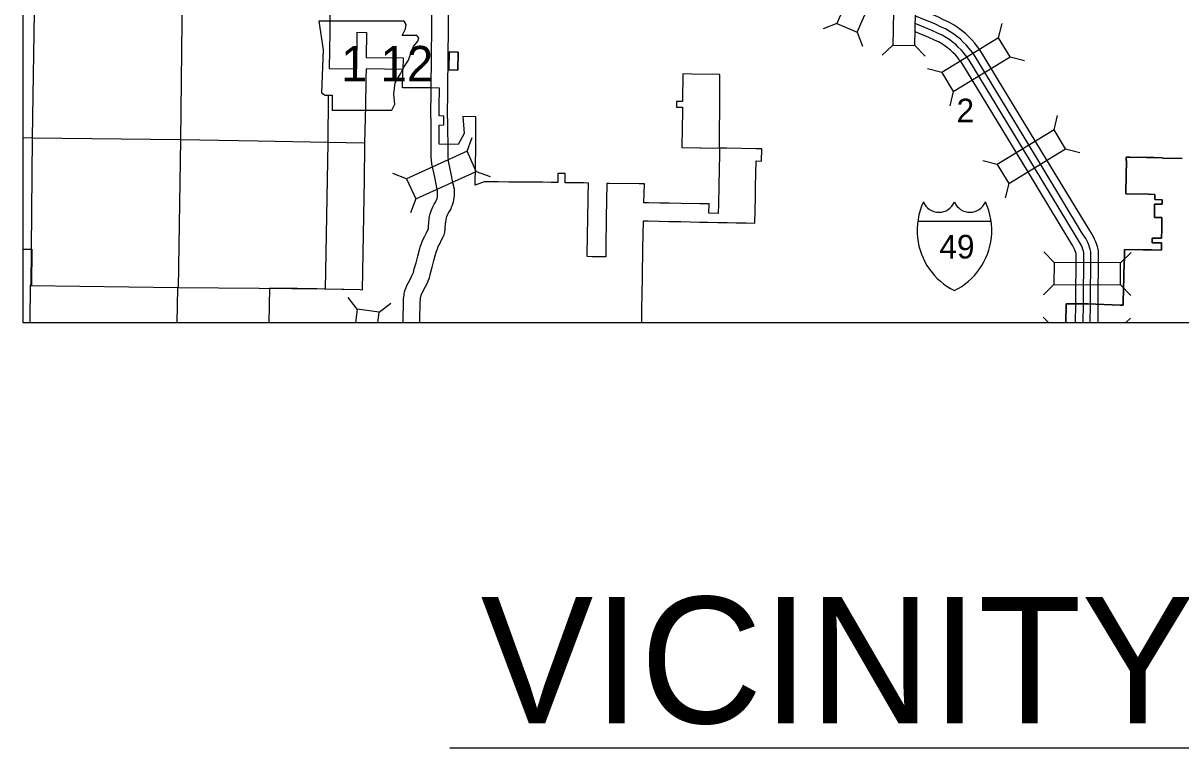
# Model space of a CAD drawing. Extents: x 309389.3 to 309420.2, y 336441.4 to 336461.2.
# Drawn here: x 309389.335 to 309392.47, y 336454.22 to 336456.181 of the extents above; entities that cross this region are included whole.
import ezdxf

# ---------------------------------------------------------------- set-up
doc = ezdxf.new("R2010")
doc.units = 0
for name, color, linetype in [('Level 1', 7, 'Continuous'), ('Level 24', 7, 'Continuous'), ('Level 37', 7, 'Continuous'), ('Level 4', 7, 'Continuous'), ('Level 48', 7, 'Continuous'), ('Level 62', 7, 'Continuous'), ('Level 63', 7, 'Continuous'), ('R_Contours', 7, 'Continuous'), ('R_Erosion', 7, 'Continuous'), ('R_MOT', 7, 'Continuous'), ('R_ROW', 7, 'Continuous')]:
    doc.layers.add(name, color=color, linetype=linetype)

msp = doc.modelspace()

# ---------------------------------------------------------------- linework, layer by layer
at = {"layer": 'Level 24'}
msp.add_line((309390.5454, 336455.969), (309390.5454, 336455.969), dxfattribs=at)
for points in [[(309390.439, 336455.9235), (309390.4424, 336456.2542), (309390.4447, 336456.4403), (309390.4463, 336456.4487), (309390.4504, 336456.4584), (309390.4579, 336456.466), (309390.4642, 336456.4703), (309390.4707, 336456.4735), (309390.4778, 336456.4762)], [(309390.4844, 336455.923), (309390.4879, 336456.2537), (309390.4901, 336456.4322), (309390.4929, 336456.4333), (309390.5042, 336456.4373), (309390.5124, 336456.4426), (309390.5169, 336456.4478)], [(309390.439, 336455.9235), (309390.4394, 336455.819), (309390.4412, 336455.8006), (309390.4488, 336455.7643), (309390.4537, 336455.7407), (309390.4565, 336455.7275), (309390.4565, 336455.7158), (309390.456, 336455.7122), (309390.455, 336455.7055), (309390.4521, 336455.6977)], [(309390.4844, 336455.923), (309390.4848, 336455.8217), (309390.4862, 336455.8075), (309390.4933, 336455.7736), (309390.4982, 336455.75), (309390.5019, 336455.7322), (309390.5019, 336455.7129), (309390.5007, 336455.7035), (309390.4993, 336455.6963), (309390.4961, 336455.686)], [(309390.3642, 336455.3696), (309390.3642, 336455.3742), (309390.3641, 336455.3928), (309390.3648, 336455.4112), (309390.3651, 336455.4286), (309390.3654, 336455.4351), (309390.3659, 336455.4398), (309390.3665, 336455.4444), (309390.3673, 336455.4487), (309390.3682, 336455.4536), (309390.3697, 336455.4593), (309390.3721, 336455.4652), (309390.3745, 336455.4708), (309390.3832, 336455.4874), (309390.3881, 336455.4969), (309390.3896, 336455.5008), (309390.3919, 336455.5064), (309390.3944, 336455.5159), (309390.3991, 336455.5326), (309390.4035, 336455.5503), (309390.4082, 336455.5671), (309390.4104, 336455.5747), (309390.4145, 336455.587), (309390.4186, 336455.5962), (309390.423, 336455.6046), (309390.4275, 336455.6139), (309390.4314, 336455.622), (309390.4324, 336455.6241), (309390.4325, 336455.6257), (309390.4326, 336455.6302), (309390.4333, 336455.6407), (309390.4347, 336455.6514), (309390.4358, 336455.6578), (309390.4371, 336455.6647), (309390.4397, 336455.6734), (309390.4443, 336455.6838), (309390.448, 336455.6907), (309390.4517, 336455.6966), (309390.4521, 336455.6977)], [(309390.4097, 336455.3696), (309390.4097, 336455.3744), (309390.4096, 336455.3922), (309390.4102, 336455.4099), (309390.4105, 336455.427), (309390.4108, 336455.4315), (309390.4111, 336455.4347), (309390.4114, 336455.4373), (309390.412, 336455.4403), (309390.4126, 336455.4439), (309390.4129, 336455.4449), (309390.4141, 336455.4478), (309390.4156, 336455.4513), (309390.4236, 336455.4664), (309390.4297, 336455.4784), (309390.4318, 336455.4839), (309390.4351, 336455.4918), (309390.4383, 336455.5041), (309390.443, 336455.5209), (309390.4475, 336455.5387), (309390.4519, 336455.5547), (309390.4539, 336455.5613), (309390.457, 336455.5706), (309390.4594, 336455.5763), (309390.4636, 336455.584), (309390.4684, 336455.5942), (309390.4725, 336455.6026), (309390.4751, 336455.6081), (309390.4772, 336455.6151), (309390.4779, 336455.6231), (309390.4781, 336455.6283), (309390.4785, 336455.6363), (309390.4797, 336455.6444), (309390.4806, 336455.6499), (309390.4814, 336455.6542), (309390.4824, 336455.6576), (309390.4851, 336455.6637), (309390.4874, 336455.668), (309390.493, 336455.677), (309390.4961, 336455.686)]]:
    msp.add_lwpolyline(points, dxfattribs=at)
at = {"layer": 'Level 37'}
for p, q in [((309391.5386, 336456.1803), (309391.5013, 336456.1657)), ((309391.9767, 336456.1411), (309391.9862, 336456.18)), ((309391.5935, 336456.1562), (309391.6081, 336456.119)), ((309391.6899, 336456.1218), (309391.6611, 336456.0941)), ((309391.7499, 336456.1206), (309391.7776, 336456.0918)), ((309392.0079, 336456.0898), (309392.0467, 336456.0803)), ((309391.8229, 336456.0477), (309391.784, 336456.0572)), ((309391.854, 336455.9964), (309391.8445, 336455.9575)), ((309392.1268, 336455.8919), (309392.1363, 336455.9308)), ((309390.5373, 336455.8343), (309390.5513, 336455.8718)), ((309392.1579, 336455.8407), (309392.1968, 336455.8312)), ((309391.9729, 336455.7985), (309391.9341, 336455.808)), ((309390.3734, 336455.7599), (309390.336, 336455.7739)), ((309390.5621, 336455.7797), (309390.5996, 336455.7657)), ((309392.0041, 336455.7472), (309391.9946, 336455.7084)), ((309390.3982, 336455.7052), (309390.3842, 336455.6678)), ((309392.127, 336455.5335), (309392.0989, 336455.562)), ((309392.3069, 336455.5323), (309392.3354, 336455.5603)), ((309392.1265, 336455.4735), (309392.0981, 336455.4454)), ((309392.3065, 336455.4723), (309392.3346, 336455.4438)), ((309390.2396, 336455.4066), (309390.2153, 336455.4384)), ((309390.2991, 336455.3988), (309390.3308, 336455.4231)), ((309392.113, 336455.3696), (309392.0975, 336455.3856)), ((309392.3206, 336455.3696), (309392.334, 336455.3827))]:
    msp.add_line(p, q, dxfattribs=at)
for points in [[(309391.5935, 336456.1562), (309391.6657, 336456.3211), (309391.6107, 336456.3452), (309391.5386, 336456.1803)], [(309391.6935, 336456.3018), (309391.6899, 336456.1218), (309391.7499, 336456.1206), (309391.7534, 336456.3006)], [(309391.854, 336455.9964), (309392.0079, 336456.0898), (309391.9767, 336456.1411), (309391.8229, 336456.0477)], [(309392.0041, 336455.7472), (309392.1579, 336455.8407), (309392.1268, 336455.8919), (309391.9729, 336455.7985)], [(309390.3982, 336455.7052), (309390.5621, 336455.7797), (309390.5373, 336455.8343), (309390.3734, 336455.7599)], [(309392.1265, 336455.4735), (309392.3065, 336455.4723), (309392.3069, 336455.5323), (309392.127, 336455.5335)]]:
    msp.add_lwpolyline(points, close=True, dxfattribs=at)
msp.add_lwpolyline([(309390.2952, 336455.3696), (309390.2991, 336455.3988), (309390.2396, 336455.4066), (309390.2347, 336455.3696)], dxfattribs=at)
at = {"layer": 'Level 4'}
for points in [[(309389.7714, 336456.7636), (309389.7706, 336456.6632), (309389.766, 336456.2656), (309389.7616, 336455.8654), (309389.7546, 336455.4639)], [(309389.3572, 336455.4699), (309389.3608, 336455.8707), (309389.3666, 336456.2688), (309389.3681, 336456.467)], [(309390.1614, 336455.9839), (309390.16, 336455.8571), (309390.1532, 336455.4597)], [(309389.9711, 336455.8616), (309389.7612, 336455.8655), (309389.3605, 336455.87), (309389.3351, 336455.8704)], [(309390.2603, 336455.8563), (309390.1597, 336455.858), (309389.9711, 336455.8616)], [(309389.3549, 336455.4627), (309389.3551, 336455.47)], [(309389.7531, 336455.4642), (309389.7516, 336455.3696)]]:
    msp.add_lwpolyline(points, dxfattribs=at)
at = {"layer": 'Level 48'}
for points in [[(309389.9745, 336455.4627), (309389.7536, 336455.4642), (309389.3558, 336455.4702), (309389.3542, 336455.4702)], [(309390.1507, 336455.4608), (309389.9745, 336455.4627)]]:
    msp.add_lwpolyline(points, dxfattribs=at)
at = {"layer": 'Level 62'}
for points in [[(309390.3681, 336456.4556), (309390.3532, 336456.4559), (309390.2938, 336456.457), (309390.2933, 336456.4094), (309390.2926, 336456.3561), (309390.3666, 336456.3549), (309390.3656, 336456.2793), (309390.3653, 336456.2551), (309390.2663, 336456.2569), (309390.1664, 336456.2575), (309390.1654, 336456.1577), (309390.1645, 336456.1081), (309390.1637, 336456.0585), (309390.2387, 336456.0577), (309390.24, 336456.1563), (309390.2653, 336456.1558), (309390.2641, 336456.0881), (309390.3639, 336456.0872), (309390.3635, 336456.0559)], [(309390.4619, 336455.9298), (309390.4619, 336455.9562), (309390.4625, 336456.0053), (309390.437, 336456.0056), (309390.3628, 336456.0062), (309390.3635, 336456.0559), (309390.3137, 336456.0567), (309390.2636, 336456.0574), (309390.2633, 336456.032), (309390.2632, 336456.0241), (309390.2624, 336455.9579), (309390.2597, 336455.8565), (309390.2593, 336455.8248), (309390.2593, 336455.8212), (309390.2588, 336455.7864), (309390.2585, 336455.7575), (309390.2565, 336455.6587), (309390.2553, 336455.5591), (309390.2529, 336455.4586), (309390.2475, 336455.4588), (309390.2039, 336455.46), (309390.2033, 336455.46), (309390.1981, 336455.4601), (309390.1518, 336455.4614), (309390.1304, 336455.4617), (309390.127, 336455.4617), (309390.1141, 336455.4619), (309390.104, 336455.4621), (309390.1019, 336455.4621), (309390.0769, 336455.4625), (309390.054, 336455.4628), (309390.0519, 336455.4628), (309390.0024, 336455.4634), (309390.0009, 336455.3696)], [(309390.9222, 336455.7473), (309390.9221, 336455.7473), (309390.916, 336455.7474), (309390.9144, 336455.6549), (309390.9143, 336455.6478), (309390.9132, 336455.5802), (309390.9131, 336455.5731), (309390.9127, 336455.5481), (309390.9126, 336455.5481), (309390.911, 336455.5482), (309390.9035, 336455.5483), (309390.8971, 336455.5484), (309390.8906, 336455.5486), (309390.8842, 336455.5487), (309390.8765, 336455.5489), (309390.8624, 336455.5491), (309390.8627, 336455.5635), (309390.8628, 336455.57), (309390.8629, 336455.5763), (309390.8631, 336455.5845), (309390.8633, 336455.5994), (309390.8635, 336455.6073), (309390.8636, 336455.6137), (309390.8637, 336455.6202), (309390.8638, 336455.6266), (309390.8639, 336455.6323), (309390.8639, 336455.633), (309390.864, 336455.6379), (309390.8641, 336455.6395), (309390.8641, 336455.6437), (309390.8642, 336455.6459), (309390.8643, 336455.6521), (309390.8643, 336455.6535), (309390.8644, 336455.6606), (309390.8644, 336455.661), (309390.8645, 336455.667), (309390.8645, 336455.6675), (309390.8646, 336455.6726), (309390.8647, 336455.6739), (309390.8647, 336455.6783), (309390.8648, 336455.6803), (309390.8648, 336455.685), (309390.8649, 336455.6867), (309390.865, 336455.691), (309390.865, 336455.6932), (309390.865, 336455.6963), (309390.8651, 336455.6996), (309390.8651, 336455.7016), (309390.8652, 336455.7061), (309390.8652, 336455.7069), (309390.8653, 336455.7122), (309390.8653, 336455.7125), (309390.8654, 336455.7175), (309390.8654, 336455.7189), (309390.8655, 336455.7228), (309390.8655, 336455.7255), (309390.8656, 336455.7281), (309390.8657, 336455.7319), (309390.8657, 336455.7334), (309390.8658, 336455.7383), (309390.8658, 336455.7388), (309390.8659, 336455.7459), (309390.8659, 336455.7482), (309390.8531, 336455.7484), (309390.8159, 336455.749), (309390.8148, 336455.7491), (309390.8029, 336455.7492), (309390.8029, 336455.7506), (309390.8031, 336455.7632), (309390.8032, 336455.7686), (309390.8033, 336455.7738), (309390.8033, 336455.7741), (309390.7832, 336455.7745), (309390.7827, 336455.7495), (309390.7651, 336455.7498), (309390.7419, 336455.7502), (309390.7143, 336455.7506), (309390.6618, 336455.751), (309390.6503, 336455.751), (309390.6211, 336455.7512), (309390.6157, 336455.7513), (309390.595, 336455.7514), (309390.5883, 336455.7515), (309390.5837, 336455.7515), (309390.5593, 336455.7424), (309390.5594, 336455.7518), (309390.56, 336455.7865), (309390.5612, 336455.8517), (309390.5611, 336455.8551), (309390.5611, 336455.8567), (309390.5612, 336455.8572), (309390.5613, 336455.9274), (309390.5262, 336455.9283), (309390.5298, 336455.8825), (309390.5133, 336455.8524), (309390.4617, 336455.8533), (309390.4618, 336455.9052), (309390.4744, 336455.9054), (309390.4741, 336455.9295), (309390.4619, 336455.9298)], [(309391.2208, 336455.8424), (309391.2205, 336455.8251), (309391.2198, 336455.7847), (309391.2189, 336455.7423), (309391.2189, 336455.7387), (309391.2179, 336455.6922), (309391.2179, 336455.691), (309391.217, 336455.6657), (309391.1919, 336455.6664), (309391.1927, 336455.6916), (309391.1674, 336455.6923), (309391.1167, 336455.6929), (309391.0846, 336455.6935), (309391.0597, 336455.6939), (309391.0283, 336455.6946), (309391.0159, 336455.6949), (309391.0177, 336455.7457), (309391.0035, 336455.7459), (309390.9222, 336455.7473)], [(309391.0108, 336455.3696), (309391.0108, 336455.3961), (309391.0109, 336455.4076), (309391.0109, 336455.4117), (309391.0109, 336455.4148), (309391.011, 336455.4201), (309391.011, 336455.4254), (309391.0111, 336455.4307), (309391.0111, 336455.4361), (309391.0112, 336455.4424), (309391.0112, 336455.4443), (309391.0121, 336455.4963), (309391.0126, 336455.5211), (309391.013, 336455.5461), (309391.0135, 336455.5711), (309391.0148, 336455.646), (309391.0273, 336455.6457), (309391.0572, 336455.6451), (309391.0579, 336455.6451), (309391.0837, 336455.6446), (309391.0844, 336455.6446), (309391.116, 336455.644), (309391.1665, 336455.6427), (309391.1672, 336455.6427), (309391.1894, 336455.6421), (309391.2161, 336455.6415), (309391.2295, 336455.6412), (309391.242, 336455.641), (309391.2663, 336455.6406), (309391.2677, 336455.6405), (309391.2927, 336455.6401), (309391.3169, 336455.6397), (309391.3183, 336455.7104), (309391.3188, 336455.7382), (309391.3198, 336455.8084), (309391.3343, 336455.8078), (309391.3357, 336455.8405), (309391.3218, 336455.8409), (309391.3206, 336455.8409), (309391.2399, 336455.8422), (309391.2208, 336455.8424)], [(309392.1597, 336455.4216), (309392.1959, 336455.4214), (309392.2126, 336455.4213), (309392.2173, 336455.4211), (309392.2186, 336455.4211), (309392.3061, 336455.418), (309392.3136, 336455.4177), (309392.3149, 336455.4689), (309392.3154, 336455.4846), (309392.3161, 336455.5137), (309392.3163, 336455.5188), (309392.3173, 336455.5563), (309392.3176, 336455.5688), (309392.3676, 336455.5678), (309392.391, 336455.5674), (309392.4175, 336455.5668), (309392.4178, 336455.5867), (309392.3927, 336455.5867), (309392.3929, 336455.5994), (309392.4181, 336455.599), (309392.4182, 336455.6067), (309392.4184, 336455.6154), (309392.4185, 336455.6248), (309392.4186, 336455.6262), (309392.4188, 336455.6384), (309392.4188, 336455.6385), (309392.4188, 336455.6399), (309392.4189, 336455.6424), (309392.4191, 336455.6535), (309392.4191, 336455.655), (309392.3988, 336455.6552), (309392.399, 336455.6791), (309392.3993, 336455.6913), (309392.4198, 336455.6908), (309392.4198, 336455.6943), (309392.4199, 336455.6958), (309392.42, 336455.7013), (309392.42, 336455.7028), (309392.3995, 336455.7033), (309392.4002, 336455.7174), (309392.3823, 336455.7177), (309392.3214, 336455.7187), (309392.3225, 336455.7722), (309392.3232, 336455.8047), (309392.3232, 336455.8056), (309392.3232, 336455.8088), (309392.322, 336455.8085), (309392.3221, 336455.8148), (309392.3221, 336455.8185), (309392.3234, 336455.8185), (309392.3272, 336455.8185), (309392.3318, 336455.8184), (309392.3774, 336455.8176), (309392.3975, 336455.8172), (309392.4207, 336455.8168), (309392.4207, 336455.8154), (309392.474, 336455.8143)], [(309392.474, 336455.8143), (309392.4207, 336455.8154), (309392.4207, 336455.8168), (309392.3975, 336455.8172), (309392.3774, 336455.8176), (309392.3318, 336455.8184), (309392.3272, 336455.8185), (309392.3234, 336455.8185), (309392.3221, 336455.8185), (309392.3221, 336455.8148), (309392.322, 336455.8085), (309392.3232, 336455.8088), (309392.3232, 336455.8056), (309392.3232, 336455.8047), (309392.3225, 336455.7722), (309392.3214, 336455.7187), (309392.3823, 336455.7177), (309392.4002, 336455.7174), (309392.3995, 336455.7033), (309392.42, 336455.7028), (309392.42, 336455.7013), (309392.4199, 336455.6958), (309392.4198, 336455.6943), (309392.4198, 336455.6908), (309392.3993, 336455.6913), (309392.399, 336455.6791), (309392.3988, 336455.6552), (309392.4191, 336455.655), (309392.4191, 336455.6535), (309392.4189, 336455.6424), (309392.4188, 336455.6399), (309392.4188, 336455.6385), (309392.4188, 336455.6384), (309392.4186, 336455.6262), (309392.4185, 336455.6248), (309392.4184, 336455.6154), (309392.4182, 336455.6067), (309392.4181, 336455.599), (309392.3929, 336455.5994), (309392.3927, 336455.5867), (309392.4178, 336455.5867), (309392.4175, 336455.5668), (309392.391, 336455.5674), (309392.3676, 336455.5678), (309392.3176, 336455.5688), (309392.3173, 336455.5563), (309392.3163, 336455.5188), (309392.3161, 336455.5137), (309392.3154, 336455.4846), (309392.3149, 336455.4689), (309392.3136, 336455.4177), (309392.3061, 336455.418), (309392.2186, 336455.4211), (309392.2173, 336455.4211), (309392.2126, 336455.4213), (309392.1959, 336455.4214)], [(309389.3351, 336455.5695), (309389.3585, 336455.5691), (309389.3576, 336455.4719), (309389.3542, 336455.4719), (309389.3528, 336455.3736), (309389.3527, 336455.3696)], [(309392.1959, 336455.4214), (309392.1597, 336455.4216), (309392.1591, 336455.3696)], [(309392.1591, 336455.3696), (309392.1597, 336455.4216)]]:
    msp.add_lwpolyline(points, dxfattribs=at)
for points in [[(309390.5123, 336456.054), (309390.488, 336456.0544), (309390.4887, 336456.1036), (309390.5131, 336456.1028)], [(309390.5123, 336456.054), (309390.5131, 336456.1028), (309390.4887, 336456.1036), (309390.488, 336456.0544)], [(309391.2208, 336455.8424), (309391.2208, 336455.843), (309391.2211, 336455.8939), (309391.2214, 336455.943), (309391.2219, 336455.992), (309391.2221, 336456.0196), (309391.2222, 336456.0407), (309391.2222, 336456.0419), (309391.1462, 336456.0433), (309391.1219, 336456.0437), (309391.1213, 336456.0436), (309391.1205, 336455.9704), (309391.1205, 336455.9692), (309391.1185, 336455.9692), (309391.1045, 336455.9692), (309391.1044, 336455.9625), (309391.1043, 336455.9607), (309391.1043, 336455.9536), (309391.1199, 336455.9536), (309391.1204, 336455.9536), (309391.1203, 336455.9445), (309391.1203, 336455.9436), (309391.1203, 336455.9402), (309391.1201, 336455.8989), (309391.1191, 336455.844), (309391.1687, 336455.8432), (309391.1698, 336455.8432), (309391.1703, 336455.8432)]]:
    msp.add_lwpolyline(points, close=True, dxfattribs=at)
at = {"layer": 'Level 63'}
msp.add_line((309390.4908, 336454.2197), (309393.4299, 336454.2197), dxfattribs=at)
at = {"layer": 'R_Contours'}
msp.add_lwpolyline([(309390.1363, 336456.186), (309390.1478, 336456.1091), (309390.1427, 336455.9925), (309390.1529, 336455.9861), (309390.1722, 336455.9861), (309390.1722, 336455.9451), (309390.3336, 336455.9451), (309390.3413, 336455.9617), (309390.3388, 336455.9887), (309390.3426, 336456.0194), (309390.3567, 336456.0438), (309390.3657, 336456.0617), (309390.3785, 336456.0809), (309390.3862, 336456.1014), (309390.3926, 336456.1181), (309390.4041, 336456.1322), (309390.4067, 336456.1412), (309390.4016, 336456.1476), (309390.3618, 336456.1476), (309390.3708, 336456.1655), (309390.3721, 336456.1771), (309390.3668, 336456.1859)], close=True, dxfattribs=at)
at = {"layer": 'R_Erosion'}
for points in [[(309392.1065, 336455.8123), (309391.9308, 336456.1017), (309391.9236, 336456.1127), (309391.9173, 336456.1202), (309391.912, 336456.1269), (309391.9041, 336456.1362), (309391.8954, 336456.1447), (309391.887, 336456.1529), (309391.8763, 336456.1612), (309391.8674, 336456.1685), (309391.856, 336456.1755), (309391.8423, 336456.1839), (309391.8279, 336456.1903), (309391.812, 336456.1978), (309391.7519, 336456.2222)], [(309392.0892, 336455.8008), (309391.9132, 336456.0906), (309391.9068, 336456.1002), (309391.9011, 336456.107), (309391.8959, 336456.1137), (309391.8888, 336456.122), (309391.8809, 336456.1298), (309391.8733, 336456.1372), (309391.8633, 336456.1449), (309391.8553, 336456.1515), (309391.8451, 336456.1578), (309391.8326, 336456.1654), (309391.8192, 336456.1713), (309391.8036, 336456.1787), (309391.7515, 336456.1999)], [(309392.0546, 336455.7811), (309391.8796, 336456.0693), (309391.8749, 336456.0764), (309391.8702, 336456.0819), (309391.8651, 336456.0885), (309391.8597, 336456.0949), (309391.8531, 336456.1014), (309391.8472, 336456.107), (309391.8384, 336456.1139), (309391.8321, 336456.1191), (309391.8244, 336456.1238), (309391.8141, 336456.1301), (309391.8027, 336456.1352), (309391.7876, 336456.1423), (309391.7506, 336456.1573)], [(309392.0729, 336455.7911), (309391.8972, 336456.0804), (309391.8917, 336456.0889), (309391.8864, 336456.0951), (309391.8812, 336456.1017), (309391.8749, 336456.1091), (309391.8676, 336456.1163), (309391.8609, 336456.1228), (309391.8514, 336456.1301), (309391.8442, 336456.1361), (309391.8352, 336456.1416), (309391.8238, 336456.1486), (309391.8113, 336456.1541), (309391.796, 336456.1614), (309391.7511, 336456.1796)], [(309392.2459, 336455.3696), (309392.2465, 336455.4213), (309392.2474, 336455.5556), (309392.2473, 336455.565), (309392.2444, 336455.5761), (309392.2423, 336455.5813), (309392.2403, 336455.5888), (309392.2366, 336455.5963), (309392.231, 336455.6078), (309392.222, 336455.6222), (309392.1065, 336455.8123)], [(309392.1852, 336455.3696), (309392.1859, 336455.4219), (309392.1868, 336455.5556), (309392.1868, 336455.5568), (309392.1867, 336455.5572), (309392.1847, 336455.5623), (309392.1834, 336455.5672), (309392.1821, 336455.5697), (309392.1779, 336455.5784), (309392.1704, 336455.5903), (309392.0546, 336455.7811)], [(309392.2061, 336455.3696), (309392.2067, 336455.4217), (309392.2076, 336455.5556), (309392.2076, 336455.5596), (309392.2065, 336455.5637), (309392.2045, 336455.5688), (309392.2029, 336455.5746), (309392.2009, 336455.5788), (309392.1962, 336455.5885), (309392.1881, 336455.6013), (309392.0729, 336455.7911)], [(309392.225, 336455.3696), (309392.2256, 336455.4215), (309392.2266, 336455.5556), (309392.2265, 336455.5622), (309392.2245, 336455.5696), (309392.2225, 336455.5748), (309392.2207, 336455.5814), (309392.2179, 336455.5871), (309392.2127, 336455.5977), (309392.2043, 336455.6112), (309392.0892, 336455.8008)]]:
    msp.add_lwpolyline(points, dxfattribs=at)
at = {"layer": 'R_MOT'}
msp.add_lwpolyline([(309389.3351, 336459.8498), (309394.8545, 336459.8498), (309394.8545, 336455.3696), (309389.3351, 336455.3696)], close=True, dxfattribs=at)
at = {"layer": 'R_ROW'}
msp.add_line((309391.7577, 336455.6451), (309391.9563, 336455.6451), dxfattribs=at)
for centre, radius, start, end in [((309391.9423, 336455.6192), 0.1864, 155.2204, 185.7928), ((309391.8151, 336455.7145), 0.0454, 202.1459, 337.3414), ((309391.8989, 336455.7145), 0.0454, 202.6586, 337.8541), ((309391.7718, 336455.6192), 0.1864, 354.2072, 24.7796), ((309391.9389, 336455.6208), 0.1831, 186.3923, 243.4571), ((309391.7752, 336455.6208), 0.1831, 296.5429, 353.6077)]:
    msp.add_arc(centre, radius, start, end, dxfattribs=at)

# ---------------------------------------------------------------- texts
at = {"layer": 'Level 1'}
msp.add_text('VICINITY MAP', height=0.342154, dxfattribs=at).set_placement((309390.5741, 336454.2861))
at = {"layer": 'Level 37'}
msp.add_text('2', height=0.064, dxfattribs=at).set_placement((309391.8628, 336455.9126))
at = {"layer": 'R_Contours'}
msp.add_text('1 12', height=0.096, dxfattribs=at).set_placement((309390.1958, 336456.0233))
at = {"layer": 'R_ROW'}
msp.add_text('49', height=0.064, dxfattribs=at).set_placement((309391.8163, 336455.544))

doc.saveas('drawing.dxf')
